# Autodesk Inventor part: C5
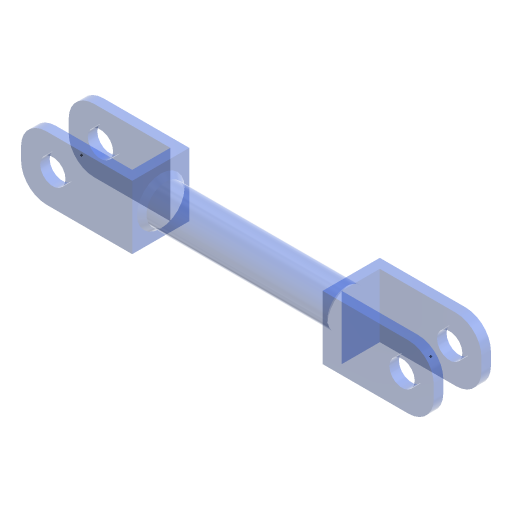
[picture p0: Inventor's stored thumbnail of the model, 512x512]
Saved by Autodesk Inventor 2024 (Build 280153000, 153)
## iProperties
Company: ATC
Shininess: 20.0
Angle Display Precision: 2
Document Length Units: 11269
Document Angle Units: 11279
Document Time Units: 11290
Document Mass Units: 11283
Document Length Units Precision: 3
Document Angle Units Precision: 2
Created: 2023-03
Part Number: C5
Material: Kurs-AJ
Document SubType Name: Modelowanie
Designer: Andrzej Jaskulski
Density: 1 g/cm^3
Appearance: Przezroczysty — niebieski
Checked By: A.J.
Engr Approved By: Andrzej Jaskulski
Mfg Approved By: Andrzej Jaskulski
Authority: A.J.
Density: 0.0
Volumn: 0.0
Area: 0.0
PropertySet Name: Model Information
Control State: 0
Master: False
Checked Out: False
Title: A.J.: Kurs R2024-MEP
Author: Andrzej Jaskulski
Revision Number: 1/24
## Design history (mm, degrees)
node "Początek"
  node "Płaszczyzna YZ"
  node "Płaszczyzna XZ"
  node "Płaszczyzna XY"
  node "Oś X"
  node "Oś Y"
  node "Oś Z"
node "Płaszczyzna konstrukcyjna1"
sketch "Szkic2"
  geometry: L1 (61.629, 12)-(29.629, 12); L2 (29.629, 0)-(61.629, 0); L3 (61.629, -3)-(26.629, -3); L4 (61.629, 12)-(61.629, 15); L5 (61.629, 15)-(26.629, 15); L6 (26.629, 15)-(26.629, -3); L7 (29.629, 12)-(29.629, 0); L8 (61.629, -3)-(61.629, 0)
  constraints: 16 end point, 4 parallel, 2 perpendicular
  dimensions: "d19" = 12 distance of L1.end L2.start; "d20" = 32 distance of L2.start L2.end; "d22" = 3 distance of L1.start L4.end; "d23" = 3 distance of L3.start L2.end (= d22); "d24" = 3 distance between parallel lines of L6 L7
extrude "Wyciągnięcie proste1" new body sketch "Szkic2" distance "d0" = 20; taper "d1" = 0 deg
sketch "Szkic3"
  geometry: L1 (0, 18)-(0, 0) reference; L2 (0, 18)-(-20, 18) reference; L3 (-20, 18)-(-20, 0) reference; C1 r 6 at (-10, 9)
  constraints: 1 centre point
  dimensions: "d4" = 12 diameter of C1; "d27" = 10 distance from line of C1.centre L3; "d28" = 9 distance from line of L2 C1.centre
extrude "Wyciągnięcie proste2" join sketch "Szkic3" distance "d5" = 60; taper "d6" = 0 deg
sketch "Szkic4"
  geometry: L1 (0, -20)-(35, -20) reference; L2 (35, 0)-(35, -20) reference; 1 further point
  dimensions: "d9" = 10 distance from line of L1 point (25, -10); "d10" = 10 distance from line of point (25, -10) L2
hole "Otwór1" sketch "Szkic4" diameter "d11" = 8; stored, may be unused: countersink angle "d15" = 82 deg, drill point angle "d17" = 118 deg; dims "d12" = 6, "d13" = 4, "d14" = 2, "d16" = 8
fillet "Zaokrąglenie1" dims "d18" = 8
chamfer "Faza1" distance "d25" = 1.5; stored, may be unused: second distance "d26" = 1.5, angle "d30" = 45 deg
node "Oś konstrukcyjna"
node "Oś konstrukcyjna3"
node "Płaszczyzna konstrukcyjna2"
mirror "Lustro1"
node "Oś konstrukcyjna4"
node "Przecięcie osi1"
node "Przecięcie osi2"
node "Bryła1"
node "Korpusy bryłowe"
node "Korpusy powierzchniowe"
node "Punkt środkowy"
